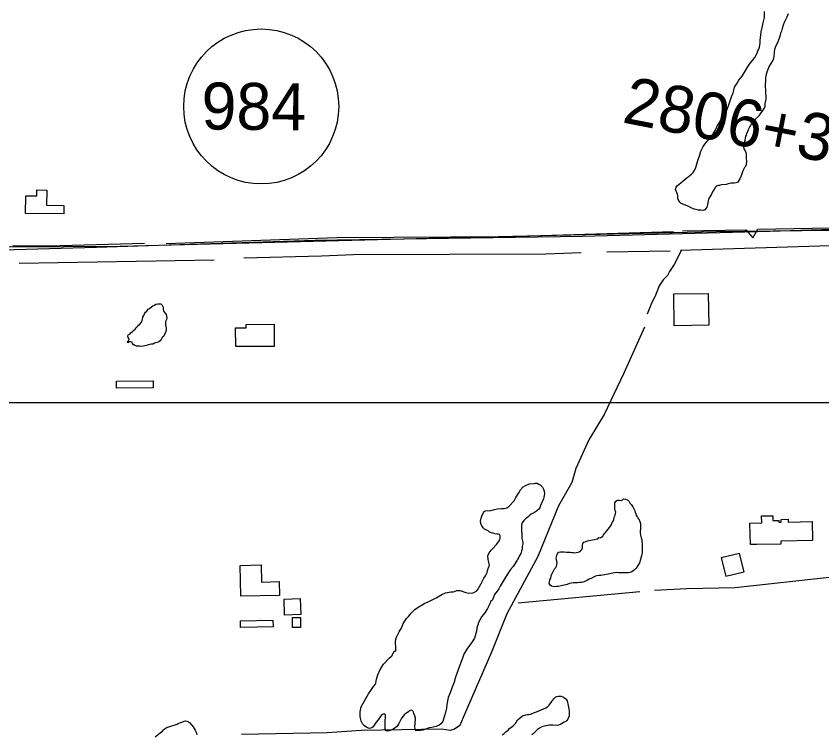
# Model space of a CAD drawing. Extents: x 3271442 to 3309282, y 752266 to 777610.
# Drawn here: x 3282653 to 3284369, y 762998 to 764526 of the extents above; entities that cross this region are included whole.
import ezdxf

# ---------------------------------------------------------------- set-up
doc = ezdxf.new("R2010")
doc.units = 0
for name, color, linetype in [('V-BLDG-OTLN', 7, 'Continuous'), ('V-GRID-MAJR', 7, 'Continuous'), ('V-ROAD-CNTR', 7, 'Continuous'), ('V-ROAD-IDEN', 7, 'Continuous'), ('V-SITE-VEGE', 7, 'Continuous'), ('V-SURV-IDEN', 7, 'Continuous'), ('V-TOPO-SHOR', 7, 'Continuous')]:
    doc.layers.add(name, color=color, linetype=linetype)

msp = doc.modelspace()

# ---------------------------------------------------------------- linework, layer by layer
at = {"layer": 'V-BLDG-OTLN'}
for points in [[(3282673.163, 764106.02), (3282673.417, 764143.63), (3282696.941, 764143.47), (3282697.0270000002, 764156.022), (3282718.035, 764155.8790000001), (3282717.818, 764123.485), (3282754.276, 764123.238), (3282754.156, 764105.475)], [(3284053.179, 763934.549), (3284126.7800000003, 763935.8910000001), (3284128.017, 763867.854), (3284054.423, 763866.515)], [(3283120.623, 763822.358), (3283120.336, 763862.621), (3283142.821, 763862.783), (3283142.77, 763869.623), (3283202.342, 763870.054), (3283202.682, 763822.948)], [(3282866.566, 763734.128), (3282866.449, 763749.197), (3282944.4620000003, 763749.795), (3282944.577, 763734.728)], [(3284216.35, 763400.701), (3284215.326, 763446.333), (3284240.764, 763446.902), (3284240.43, 763461.7440000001), (3284263.958, 763462.27), (3284264.193, 763451.762), (3284276.805, 763452.044), (3284276.889, 763448.432), (3284282.306, 763448.555), (3284282.177, 763454.305), (3284296.662, 763454.6290000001), (3284296.793, 763448.774), (3284347.825, 763449.919), (3284348.728, 763409.637), (3284281.077, 763408.1190000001), (3284281.2120000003, 763402.061), (3284230.3170000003, 763400.9180000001), (3284230.3170000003, 763401.014)], [(3284202.87955699, 763342.989286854), (3284193.3435760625, 763381.835209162), (3284154.496653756, 763372.2992282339), (3284164.033634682, 763333.452305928)], [(3283129.73, 763356.491), (3283174.624, 763357.515), (3283175.4560000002, 763321.061), (3283213.213, 763321.9230000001), (3283213.878, 763292.683), (3283131.227, 763290.797)], [(3283224.579, 763250.714), (3283223.598, 763284.78), (3283257.9, 763285.767), (3283258.879, 763251.701)], [(3283130.598, 763224.02), (3283130.3140000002, 763238.733), (3283199.864, 763240.081), (3283200.149, 763225.368)], [(3283241.117, 763245.274), (3283258.156, 763245.297), (3283258.183, 763224.127), (3283241.143, 763224.104)]]:
    msp.add_lwpolyline(points, close=True, dxfattribs=at)
at = {"layer": 'V-GRID-MAJR'}
msp.add_spline([(3275589.54, 763703.55), (3280833.333, 763703.169), (3286077.126, 763703.55), (3291320.919, 763704.694), (3296564.7120000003, 763706.601), (3301808.505, 763709.27), (3307052.2970000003, 763712.703), (3307052.298, 763712.703)], degree=3, dxfattribs=at)
at = {"layer": 'V-ROAD-CNTR'}
for points in [[(3284677.557607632, 764080.802811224), (3284257.9054469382, 764067.830837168), (3283859.2862441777, 764057.2688582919), (3283288.7283852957, 764048.6358755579), (3282823.6733154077, 764033.7179053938), (3282522.738917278, 764025.231922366), (3282076.6898093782, 764017.49493784), (3281506.195950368, 764007.1329585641), (3280959.8490430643, 763996.182980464), (3280433.671095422, 763985.9950008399), (3280185.115592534, 763990.337992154), (3279818.572325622, 763986.183000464), (3279470.4860217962, 763985.38000207), (3279084.0857945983, 763978.2810162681)], [(3279103.19975637, 763968.342036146), (3280192.2165783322, 763984.719003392), (3280439.6570834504, 763995.6009816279), (3280717.8265271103, 763999.130974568), (3280859.937242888, 764007.9109570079), (3281283.7353952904, 764018.4639359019), (3281575.6458114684, 764020.222932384), (3281793.6993753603, 764025.497921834), (3282273.7684152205, 764032.5319077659), (3282874.1462144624, 764036.44989993), (3283587.207788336, 764054.8678630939), (3284143.70467534, 764067.5718376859), (3284569.5268236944, 764072.722827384)]]:
    msp.add_lwpolyline(points, dxfattribs=at)
at = {"layer": 'V-ROAD-IDEN'}
msp.add_circle((3283174.80161315, 764333.9343049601), 164.9996700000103, dxfattribs=at)
at = {"layer": 'V-SITE-VEGE'}
for points in [[(3284058.433, 764153.704), (3284057.335, 764157.019), (3284058.078, 764161.801), (3284061.029, 764165.478), (3284068.034, 764171.351), (3284073.1920000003, 764175.39), (3284077.2430000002, 764179.064), (3284081.665, 764182.367), (3284083.877, 764183.836), (3284090.879, 764189.71), (3284094.563, 764193.384), (3284098.254, 764198.897), (3284100.47, 764203.677), (3284104.545, 764219.123), (3284108.613, 764230.524), (3284110.835, 764238.6140000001), (3284115.637, 764248.54), (3284119.6920000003, 764253.685), (3284124.489, 764260.3), (3284131.124, 764266.9130000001), (3284134.073, 764270.587), (3284138.133, 764276.836), (3284140.717, 764281.2490000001), (3284143.6720000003, 764287.8640000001), (3284145.886, 764291.909), (3284152.532, 764303.304), (3284156.9560000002, 764309.184), (3284159.54, 764313.96), (3284162.4930000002, 764319.108), (3284166.9250000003, 764327.564), (3284172.1010000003, 764341.5380000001), (3284173.952, 764347.791), (3284176.539, 764354.041), (3284179.867, 764363.234), (3284180.981, 764368.752), (3284182.83, 764374.636), (3284187.997, 764383.458), (3284192.054, 764389.707), (3284198.696, 764398.5260000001), (3284203.492, 764405.1410000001), (3284209.399, 764415.801), (3284213.0870000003, 764421.682), (3284216.776, 764426.827), (3284220.8310000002, 764431.605), (3284225.627, 764437.851), (3284230.796, 764447.041), (3284232.646, 764452.189), (3284234.489, 764455.866), (3284235.603, 764459.91), (3284237.09, 764468.371), (3284237.102, 764475.362), (3284238.591, 764485.664), (3284239.707, 764492.654), (3284241.565, 764502.22), (3284241.937, 764504.792), (3284243.4220000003, 764512.147), (3284246.3880000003, 764523.552), (3284246.4080000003, 764536.061)], [(3284297.18, 764530.8200000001), (3284293.856, 764524.203), (3284290.901, 764518.688), (3284288.319, 764512.437), (3284286.465, 764506.92)], [(3284286.465, 764506.92), (3284284.245, 764499.566), (3284282.396, 764494.0480000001), (3284280.915, 764490.0040000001), (3284280.174, 764485.959), (3284278.324, 764480.442), (3284274.628, 764471.248), (3284269.454, 764459.482), (3284267.9760000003, 764455.438), (3284266.864, 764450.289), (3284266.858, 764447.712), (3284265.733, 764436.307), (3284264.255, 764431.527), (3284262.409, 764428.586), (3284259.829, 764425.647), (3284256.507, 764419.765), (3284253.5500000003, 764412.411), (3284251.332, 764407.264), (3284249.478, 764399.171), (3284248.366, 764394.757), (3284248.3540000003, 764387.765), (3284247.975, 764381.513), (3284247.967, 764377.095), (3284248.319, 764368.262), (3284248.309, 764362.743), (3284249.398, 764355.0160000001), (3284249.394, 764352.073), (3284249.021, 764349.497), (3284248.647, 764345.4500000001), (3284248.274, 764343.242), (3284247.5330000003, 764340.301), (3284247.162, 764337.725), (3284247.154, 764334.044), (3284246.7830000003, 764331.839), (3284234.608, 764313.829), (3284231.659, 764311.258), (3284225.7600000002, 764305.7490000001), (3284221.3370000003, 764300.605), (3284218.017, 764295.829), (3284216.54, 764293.2540000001), (3284215.432, 764291.049), (3284212.85, 764286.637), (3284211.742, 764284.432), (3284211, 764282.226), (3284208.045, 764275.607), (3284207.306, 764273.032), (3284206.196, 764270.458), (3284205.086, 764266.045), (3284204.34, 764261.263), (3284202.855, 764253.537), (3284202.11, 764248.755), (3284202.47, 764243.973), (3284205.4050000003, 764239.181), (3284206.503, 764235.8690000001), (3284207.232, 764232.556), (3284207.59, 764227.036), (3284207.5840000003, 764222.987), (3284207.941, 764217.099), (3284207.56, 764209.372), (3284205.7120000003, 764205.696), (3284204.238, 764203.859), (3284200.545, 764196.507), (3284196.48, 764186.212), (3284193.893, 764179.959), (3284189.095, 764172.24), (3284186.519, 764171.14), (3284181.732, 764170.782), (3284178.423, 764170.7880000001), (3284175.844, 764170.4230000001), (3284172.164, 764169.694), (3284168.85, 764168.965), (3284165.168, 764167.868), (3284154.4960000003, 764166.782), (3284150.447, 764165.686), (3284148.237, 764165.322), (3284144.557, 764164.224), (3284142.343, 764161.654), (3284139.025, 764157.243), (3284136.81, 764153.566), (3284133.49, 764147.318), (3284131.64, 764143.273), (3284128.319, 764137.76), (3284127.579, 764135.552), (3284126.84, 764132.609), (3284125.353, 764125.255), (3284123.504, 764119.738), (3284119.813, 764113.856), (3284116.497, 764112.023), (3284110.614, 764113.137), (3284106.196, 764113.145), (3284101.0470000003, 764114.257), (3284096.634, 764115.3690000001), (3284090.015, 764118.324), (3284085.603, 764120.909), (3284069.058, 764127.192), (3284066.485, 764129.775), (3284062.8170000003, 764136.036), (3284062.086, 764138.981), (3284061.728, 764144.131), (3284059.899, 764150.392), (3284058.433, 764153.704)], [(3283659.4760000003, 763353.603), (3283660.586, 763356.544), (3283658.7630000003, 763366.483), (3283658.032, 763369.062), (3283657.68, 763377.157), (3283659.898, 763383.408), (3283664.324, 763388.919), (3283668.0100000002, 763392.593), (3283675.751, 763401.0430000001), (3283680.177, 763406.9230000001), (3283682.762, 763411.332), (3283683.505, 763415.748), (3283683.511, 763419.4280000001), (3283682.412, 763422.0040000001), (3283679.469, 763423.1140000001), (3283676.894, 763423.1190000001), (3283672.481, 763423.8640000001), (3283661.08, 763427.563), (3283657.772, 763429.777), (3283653.361, 763431.993), (3283650.42, 763433.838), (3283647.481, 763436.4180000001), (3283643.811, 763441.944), (3283642.347, 763445.995), (3283641.984, 763450.41), (3283643.102, 763457.031), (3283644.5810000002, 763461.4450000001), (3283646.799, 763466.225), (3283649.75, 763471.003), (3283652.697, 763472.838), (3283663.738, 763473.555), (3283671.838, 763475.3790000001), (3283677.728, 763477.208), (3283686.19, 763477.929), (3283692.078, 763477.552), (3283697.6, 763479.017), (3283702.021, 763481.949), (3283713.449, 763494.071), (3283717.142, 763501.057), (3283723.415, 763510.984), (3283726.738, 763517.23), (3283732.268, 763523.479), (3283737.427, 763526.778), (3283743.688, 763529.713), (3283746.264, 763530.444), (3283756.568, 763531.161), (3283758.7770000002, 763531.894), (3283762.089, 763531.519), (3283766.134, 763529.672), (3283768.7060000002, 763528.1950000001), (3283773.849, 763523.034), (3283776.048, 763518.615), (3283777.146, 763514.566), (3283777.8710000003, 763509.042), (3283777.498, 763505.733), (3283776.755, 763501.319), (3283775.645, 763498.378), (3283769.732, 763484.405), (3283767.883, 763478.89), (3283765.671, 763475.949), (3283760.879, 763471.91), (3283756.826, 763468.973), (3283753.881, 763467.876), (3283749.461, 763465.676), (3283746.881, 763463.47), (3283742.4590000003, 763459.432), (3283739.5100000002, 763457.23), (3283737.3000000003, 763455.393), (3283733.98, 763452.454), (3283732.506, 763449.882), (3283729.923, 763446.208), (3283728.809, 763439.953), (3283728.789, 763428.177), (3283729.52, 763425.601), (3283729.505, 763417.507), (3283729.8680000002, 763413.829), (3283732.059, 763405.356), (3283732.053, 763402.415), (3283730.572, 763396.898), (3283730.193, 763392.116), (3283728.715, 763387.334), (3283727.603, 763382.183), (3283724.281, 763376.3030000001), (3283722.802, 763372.625), (3283720.588, 763369.318), (3283719.48, 763367.481), (3283718.372, 763365.275), (3283714.313, 763358.289), (3283711.362, 763354.2440000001), (3283705.832, 763347.633), (3283702.877, 763343.591), (3283698.083, 763335.872), (3283696.606, 763333.299), (3283683.321, 763311.98), (3283681.103, 763306.464), (3283677.048, 763301.3200000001), (3283671.883, 763294.338), (3283669.667, 763289.1900000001), (3283667.447, 763282.939), (3283665.235, 763281.1020000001), (3283663.392, 763279.267)], [(3283498.86, 763043.6900000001), (3283497.393, 763046.637), (3283494.45, 763048.113), (3283491.876, 763047.751), (3283488.927, 763045.179), (3283485.98, 763042.9770000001), (3283483.0330000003, 763041.142), (3283479.346, 763038.203), (3283477.503, 763036.001), (3283473.815, 763031.223), (3283471.6010000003, 763027.179), (3283467.906, 763019.826), (3283465.6920000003, 763016.15), (3283463.112, 763012.843), (3283459.059, 763009.906), (3283456.112, 763008.073), (3283451.69, 763005.505), (3283446.906, 763004.04), (3283443.2260000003, 763003.68), (3283439.179, 763004.79), (3283438.45, 763008.104), (3283438.454, 763010.68), (3283438.482, 763026.8690000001), (3283439.23, 763032.755), (3283439.238, 763038.277), (3283437.401, 763039.751), (3283434.825, 763039.387), (3283430.4050000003, 763037.187), (3283428.191, 763034.248), (3283425.977, 763030.574), (3283417.495, 763019.916), (3283415.281, 763016.24), (3283413.0670000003, 763012.933), (3283410.12, 763010.363), (3283405.7, 763009.265), (3283401.289, 763010.377), (3283397.613, 763012.593), (3283394.6720000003, 763014.805), (3283390.633, 763018.86), (3283388.798, 763022.1730000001), (3283387.7, 763025.487), (3283386.238, 763031.01), (3283385.509, 763034.691), (3283385.146, 763038.371), (3283385.525, 763044.626), (3283386.269, 763047.937), (3283387.012, 763052.719), (3283388.124, 763056.4), (3283403.257, 763082.8640000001), (3283408.053, 763090.216), (3283413.9560000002, 763098.6680000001), (3283416.536, 763101.976), (3283418.0130000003, 763103.444), (3283418.752, 763105.652), (3283420.608, 763114.479), (3283423.198, 763123.306), (3283428.003, 763134.705), (3283435.384, 763146.466), (3283447.918, 763159.6900000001), (3283453.077, 763164.098), (3283458.614, 763174.758), (3283461.557, 763174.0160000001), (3283461.1950000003, 763176.226), (3283461.201, 763180.6410000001), (3283460.488, 763193.89), (3283461.602, 763199.039), (3283463.0810000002, 763203.821), (3283465.2970000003, 763207.863), (3283468.623, 763214.849), (3283470.8370000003, 763218.894), (3283473.419, 763222.568), (3283477.116, 763232.497), (3283484.495, 763243.523), (3283488.181, 763247.564), (3283494.082, 763254.546), (3283502.1920000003, 763262.627), (3283506.982, 763265.9280000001), (3283512.507, 763269.9670000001), (3283516.558, 763271.8), (3283521.715, 763275.103), (3283530.554, 763279.134), (3283547.495, 763287.566), (3283559.6520000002, 763294.537), (3283567.386, 763298.203), (3283578.7970000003, 763300.023), (3283583.948, 763300.382), (3283591.681, 763303.311), (3283598.304, 763303.3), (3283610.4390000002, 763298.496), (3283616.691, 763297.013), (3283625.893, 763297.732), (3283629.207, 763299.5650000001), (3283633.628, 763302.502), (3283635.84, 763305.4400000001), (3283639.5330000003, 763311.693), (3283642.117, 763316.838), (3283648.7630000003, 763328.968), (3283652.083, 763334.1140000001), (3283656.144, 763341.4670000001), (3283657.627, 763347.719), (3283659.4760000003, 763353.603)], [(3283663.392, 763279.267), (3283662.6520000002, 763276.693), (3283659.6950000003, 763270.074), (3283656.744, 763264.927), (3283651.948, 763257.208), (3283647.8880000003, 763252.063), (3283644.202, 763246.919), (3283637.556, 763234.789), (3283634.222, 763222.65), (3283633.477, 763216.764), (3283628.666, 763201.687), (3283624.234, 763193.599), (3283612.431, 763177.799), (3283606.5270000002, 763167.137), (3283603.568, 763158.679), (3283597.653, 763144.337), (3283588.7770000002, 763118.595), (3283585.8140000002, 763107.563), (3283581.7460000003, 763096.899), (3283576.944, 763085.131), (3283573.245, 763074.836), (3283570.275, 763060.121), (3283569.157, 763052.3960000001), (3283566.933, 763043.2000000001), (3283563.228, 763028.856), (3283561.379, 763024.076), (3283557.324, 763018.931), (3283554.006, 763016.361), (3283547.0100000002, 763013.43), (3283540.751, 763012.337), (3283537.806, 763011.606), (3283532.287, 763010.512), (3283524.554, 763007.583), (3283519.0300000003, 763005.753), (3283513.878, 763005.025), (3283505.045, 763004.305), (3283502.841, 763007.252), (3283502.1180000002, 763013.8790000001), (3283502.863, 763019.3960000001), (3283502.87, 763022.339), (3283503.242, 763026.02), (3283503.253, 763031.1680000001), (3283501.788, 763035.956), (3283499.591, 763041.111), (3283498.86, 763043.6900000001)], [(3283687.544, 762995.519), (3283691.963, 762998.822), (3283695.65, 763002.128), (3283700.44, 763005.7980000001), (3283703.758, 763009.101), (3283709.285, 763013.51), (3283711.866, 763015.714), (3283716.288, 763019.753), (3283717.762, 763021.958), (3283719.241, 763024.531), (3283720.715, 763026.736), (3283723.296, 763029.675), (3283731.035, 763035.9180000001), (3283733.614, 763037.017), (3283738.4, 763038.48), (3283741.343, 763038.8420000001), (3283743.919, 763038.838), (3283748.705, 763039.934), (3283753.125, 763041.767), (3283764.538, 763046.162), (3283769.327, 763048.361), (3283777.426, 763051.658), (3283780.742, 763053.491), (3283784.424, 763055.322), (3283786.636, 763057.161), (3283788.111, 763058.63), (3283789.5870000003, 763061.204), (3283792.17, 763064.512), (3283794.015, 763067.817), (3283795.49, 763069.656), (3283798.0700000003, 763072.229), (3283799.545, 763074.066), (3283802.125, 763076.267), (3283803.967, 763077.3690000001), (3283806.912, 763078.1), (3283809.119, 763078.096), (3283813.535, 763077.721), (3283818.313, 763075.872), (3283823.461, 763072.55), (3283826.0300000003, 763068.13), (3283828.588, 763058.192), (3283830.046, 763050.829), (3283830.404, 763045.676), (3283830.758, 763038.316), (3283830.3880000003, 763035.741), (3283829.278, 763033.169), (3283827.799, 763028.756), (3283825.585, 763026.181), (3283823.375, 763024.346), (3283819.691, 763022.513), (3283812.693, 763018.11), (3283807.909, 763016.279), (3283801.648, 763015.554), (3283795.762, 763016.3), (3283788.406, 763016.312), (3283785.4590000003, 763015.583), (3283781.776, 763014.485), (3283778.096, 763014.125), (3283772.2060000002, 763012.662), (3283767.418, 763010.094), (3283763.365, 763007.157), (3283757.8370000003, 763002.017), (3283754.518, 762998.343), (3283751.202, 762995.406)], [(3282949.019, 762991.679), (3282959.703, 762999.7540000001), (3282964.495, 763003.7930000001), (3282966.707, 763005.996), (3282968.182, 763007.835), (3282974.813, 763012.2390000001), (3282977.758, 763012.97), (3282995.7970000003, 763018.456), (3282998.009, 763019.556), (3283001.323, 763021.3910000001), (3283007.5810000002, 763023.22), (3283010.897, 763025.0530000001), (3283013.105, 763025.417), (3283016.416, 763025.045), (3283019.7260000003, 763023.197), (3283021.93, 763021.723), (3283026.341, 763017.299), (3283029.64, 763012.509), (3283034.043, 763005.511), (3283036.2430000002, 763001.089), (3283037.707, 762996.3030000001)]]:
    msp.add_lwpolyline(points, dxfattribs=at)
at = {"layer": 'V-TOPO-SHOR'}
for p, q in [((3284067.967494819, 764027.9570811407), (3284668.964833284, 764046.9038768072)), ((3283910.897910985, 764024.1300270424), (3284045.7647806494, 764026.433025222)), ((3282659.5179342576, 764000.298696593), (3283074.359461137, 764007.1233386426)), ((3283980.693868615, 763300.5076235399), (3283721.687038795, 763276.3450330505))]:
    msp.add_line(p, q, dxfattribs=at)
for points in [[(3284071.7185440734, 764068.8926351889), (3284206.5854137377, 764071.1956333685), (3284221.806203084, 764054.0009081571), (3284232.2017672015, 764072.6915717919), (3284618.027360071, 764079.7552125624), (3284689.7700202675, 764085.9920237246), (3284722.31206356, 764099.3794646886), (3284725.781937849, 764106.1786257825), (3284737.926497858, 764129.9756896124), (3284741.551018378, 764155.5498668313), (3284750.3944090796, 764193.0296053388)], [(3282972.2314572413, 764042.1032564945), (3283335.9105709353, 764054.4701199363), (3283699.5053321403, 764056.59606549), (3284052.9294691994, 764067.3404617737)], [(3282646.172669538, 764037.9611988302), (3282721.272734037, 764037.3426139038), (3282926.1473267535, 764042.4828426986)], [(3284069.7240275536, 764027.7577566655), (3284054.2502945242, 763997.4372335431), (3284044.4375703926, 763982.2940704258), (3284040.2174613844, 763974.0248368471), (3284030.4503331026, 763964.4172940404), (3284022.0443119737, 763952.0305421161), (3284013.5584981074, 763929.9564546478), (3284006.524983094, 763916.1743986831), (3283996.6324662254, 763891.3439000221)], [(3283137.553964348, 764011.7236238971), (3283303.1576464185, 764015.4803842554), (3283371.458549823, 764018.3316736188), (3283781.137441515, 764020.07803297), (3283856.2656235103, 764022.8730873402)], [(3282947.563, 763829.55), (3282944.247, 763827.715), (3282940.5670000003, 763827.355), (3282937.255, 763826.992), (3282933.941, 763825.895), (3282930.259, 763824.799), (3282926.9450000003, 763824.068), (3282924, 763823.337), (3282919.585, 763822.976), (3282916.273, 763823.351), (3282912.595, 763823.357), (3282909.281, 763823.363), (3282905.974, 763824.8420000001), (3282902.298, 763826.687), (3282900.461, 763829.2660000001), (3282899.731, 763832.211), (3282896.789, 763832.952), (3282893.477, 763832.59), (3282890.896, 763830.388), (3282889.7970000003, 763833.333), (3282892.744, 763835.1680000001), (3282893.485, 763838.111), (3282891.6520000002, 763841.7930000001), (3282890.554, 763845.473), (3282892.4, 763848.0480000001), (3282895.345, 763849.1460000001), (3282897.927, 763852.453), (3282900.874, 763854.286), (3282903.086, 763856.492), (3282906.035, 763859.431), (3282908.616, 763862.736), (3282911.196, 763865.308), (3282913.4080000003, 763867.881), (3282916.357, 763870.451), (3282920.044, 763874.492), (3282921.522, 763877.801), (3282921.897, 763881.113), (3282923.007, 763885.158), (3282924.486, 763888.4670000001), (3282926.333, 763892.512), (3282928.545, 763895.451), (3282931.125, 763898.0210000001), (3282934.076, 763902.066), (3282936.6550000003, 763903.9010000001), (3282941.077, 763907.204), (3282943.657, 763909.039), (3282947.339, 763910.872), (3282950.6550000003, 763912.705), (3282954.335, 763913.436), (3282958.0160000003, 763913.797), (3282961.325, 763913.422), (3282963.897, 763910.844), (3282964.995, 763907.897), (3282965.7260000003, 763904.951), (3282966.0870000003, 763900.905), (3282966.818, 763897.96), (3282970.1210000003, 763893.5380000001), (3282972.325, 763890.591), (3282973.423, 763887.275), (3282973.785, 763883.964), (3282973.042, 763880.285), (3282971.934, 763877.3420000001), (3282970.824, 763874.4010000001), (3282971.182, 763869.2490000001), (3282971.911, 763864.831), (3282972.274, 763861.52), (3282972.2660000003, 763857.839), (3282971.893, 763854.53), (3282969.677, 763849.75), (3282967.09, 763844.603), (3282964.143, 763842.033), (3282961.559, 763837.621), (3282959.347, 763834.681), (3282956.7660000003, 763832.846), (3282953.453, 763831.013), (3282947.563, 763829.55)], [(3283990.8688666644, 763863.7113943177), (3283947.158482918, 763765.8075016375), (3283904.9117969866, 763677.5795455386), (3283872.6374206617, 763623.8694236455), (3283844.4577647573, 763563.2055794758), (3283835.9035571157, 763532.8280615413), (3283807.8150929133, 763483.2354579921), (3283764.0249164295, 763375.6442297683), (3283697.966870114, 763253.012429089), (3283665.4645145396, 763171.6242056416), (3283604.8053009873, 763032.3399481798), (3283597.7489880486, 763015.7900820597), (3283586.6093536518, 763007.5778432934), (3283576.8992201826, 763004.8898258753), (3283558.9312520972, 763007.8058225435), (3283387.2928255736, 763005.06757866), (3283315.2841656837, 763000.1247043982), (3283132.5630995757, 762996.0937471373)], [(3283899.506, 763416.469), (3283902.0840000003, 763419.041), (3283903.929, 763421.613), (3283906.512, 763424.921), (3283908.724, 763427.491), (3283910.936, 763430.063), (3283913.887, 763433.371), (3283916.467, 763437.045), (3283918.681, 763439.986), (3283920.528, 763443.662), (3283922.376, 763447.707), (3283924.221, 763450.6460000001), (3283925.698, 763453.955), (3283926.441, 763457.633), (3283927.18, 763460.576), (3283928.29, 763463.517), (3283929.4, 763466.829), (3283929.773, 763470.139), (3283928.6750000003, 763473.084), (3283927.946, 763477.501), (3283927.586, 763481.55), (3283927.594, 763485.5970000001), (3283927.969, 763489.644), (3283929.8140000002, 763492.953), (3283933.498, 763495.155), (3283936.81, 763495.149), (3283941.2260000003, 763494.772), (3283944.171, 763495.872), (3283946.0160000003, 763498.444), (3283949.694, 763497.701), (3283954.474, 763495.853), (3283958.146, 763492.535), (3283960.348, 763488.482), (3283963.287, 763485.167), (3283966.223, 763481.48), (3283968.054, 763477.063), (3283970.256, 763473.012), (3283970.985, 763470.067), (3283972.451, 763466.0160000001), (3283973.549, 763462.702), (3283975.751, 763459.018), (3283977.586, 763456.439), (3283979.421, 763453.859), (3283981.254, 763450.177), (3283982.349, 763445.759), (3283982.7120000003, 763442.079), (3283982.335, 763437.6630000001), (3283982.3310000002, 763434.3520000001), (3283981.954, 763429.5700000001), (3283981.948, 763426.258), (3283982.6750000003, 763420.737), (3283983.769, 763415.215), (3283985.233, 763410.7980000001), (3283985.593, 763407.118), (3283985.9560000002, 763403.804), (3283986.312, 763397.547), (3283986.302, 763392.03), (3283986.294, 763386.877), (3283985.919, 763383.566), (3283985.178, 763380.623), (3283984.434, 763376.578), (3283983.324, 763372.9), (3283982.583, 763369.221), (3283980.363, 763361.867), (3283978.515, 763358.557), (3283976.67, 763355.985), (3283974.458, 763353.044), (3283972.613, 763349.737), (3283970.0330000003, 763347.164), (3283967.086, 763344.963), (3283963.77, 763342.761), (3283960.088, 763341.6630000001), (3283956.039, 763340.934), (3283951.623, 763340.943), (3283947.943, 763340.949), (3283943.5270000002, 763340.957), (3283939.847, 763340.963), (3283935.8000000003, 763340.969), (3283932.12, 763341.346), (3283927.338, 763340.986), (3283923.287, 763340.256), (3283920.342, 763339.525), (3283917.0300000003, 763338.796), (3283913.348, 763337.698), (3283909.668, 763336.969), (3283905.619, 763336.24), (3283901.568, 763335.511), (3283897.89, 763335.1510000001), (3283894.208, 763334.7880000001), (3283889.79, 763334.061), (3283886.847, 763333.33), (3283882.427, 763331.497), (3283877.639, 763328.931), (3283873.22, 763327.098), (3283869.537, 763324.8960000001), (3283864.014, 763322.33), (3283859.963, 763320.866), (3283856.649, 763320.137), (3283852.6, 763319.7760000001), (3283848.185, 763319.047), (3283844.505, 763319.422)], [(3283844.505, 763319.422), (3283840.089, 763319.43), (3283834.568, 763318.703), (3283831.254, 763317.974), (3283826.47, 763316.1410000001), (3283823.525, 763315.412), (3283820.2090000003, 763314.681), (3283816.529, 763313.583), (3283813.215, 763312.854), (3283807.325, 763311.761), (3283803.647, 763311.398), (3283800.333, 763311.0380000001), (3283796.287, 763311.412), (3283792.977, 763312.522), (3283790.036, 763314.734), (3283788.201, 763317.681), (3283788.944, 763320.993), (3283789.688, 763325.406), (3283791.167, 763329.085), (3283792.281, 763334.6020000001), (3283793.757, 763337.911), (3283795.605, 763341.954), (3283797.452, 763345.264), (3283799.666, 763349.307), (3283801.88, 763352.247), (3283803.725, 763355.188), (3283804.464, 763358.1290000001), (3283804.839, 763361.81), (3283804.11, 763365.49), (3283803.381, 763368.804), (3283802.65, 763371.7490000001), (3283803.3910000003, 763375.058), (3283804.132, 763378.001), (3283805.978, 763381.311), (3283808.1920000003, 763384.616), (3283812.24, 763385.714), (3283816.6580000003, 763385.706), (3283819.968, 763385.333), (3283825.1180000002, 763384.954), (3283829.165, 763384.579), (3283832.4790000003, 763384.942), (3283836.157, 763384.2000000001), (3283839.835, 763384.192), (3283842.778, 763383.084), (3283845.723, 763383.8150000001), (3283849.037, 763384.9130000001), (3283851.982, 763385.644), (3283854.56, 763387.479), (3283857.509, 763390.416), (3283858.619, 763393.728), (3283858.63, 763399.247), (3283859.3710000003, 763402.925), (3283861.585, 763405.8640000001), (3283864.899, 763406.964), (3283869.687, 763408.795), (3283872.632, 763409.5260000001), (3283876.679, 763409.886), (3283880.361, 763410.615), (3283884.41, 763411.345), (3283887.724, 763412.442), (3283891.772, 763413.171), (3283893.984, 763415.7440000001), (3283896.927, 763415), (3283899.506, 763416.469)], [(3284576.468388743, 763380.0242794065), (3284563.7168700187, 763344.1453380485), (3284390.6147456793, 763331.731157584), (3284184.2077077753, 763308.5193115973), (3284080.392029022, 763306.6064236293), (3284012.5464833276, 763303.0132575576)]]:
    msp.add_lwpolyline(points, dxfattribs=at)

# ---------------------------------------------------------------- texts
at = {"layer": 'V-ROAD-IDEN'}
msp.add_text('984', height=100.00019799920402, rotation=359.52816776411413, dxfattribs=at).set_placement((3283047.2298682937, 764284.9834028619))
at = {"layer": 'V-SURV-IDEN'}
msp.add_text('2806+35.8', height=100, rotation=348.9100000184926, dxfattribs=at).set_placement((3283941.156329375, 764300.2964325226))

doc.saveas('drawing.dxf')
